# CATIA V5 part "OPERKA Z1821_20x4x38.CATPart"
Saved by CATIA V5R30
Part number: OPERKA MENSI Z1821/20x4x38
Bounding box of the stored display mesh (mm): x -7.677 to 3.495, y -9.397 to 9.603, z -19 to 19
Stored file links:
  C:\Users\ondra\Desktop\PŘÍLOHA P III\CATIA\OPERKA Z1821_20x4x38.CATPart
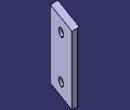
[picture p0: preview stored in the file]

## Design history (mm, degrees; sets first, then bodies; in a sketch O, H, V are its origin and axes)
Set1
  DatumSurface1 to DatumSurface19 "Z1821/20"
  Plane1: type Tangent, Support DatumSurface15, RefPoint vertex [face of DatumSurface19]
  Plane2: type Tangent, Support DatumSurface14, RefPoint vertex [face of DatumSurface18]
  Plane3: type Tangent, Support DatumSurface18, RefPoint vertex [face of DatumSurface18]
  Plane4: type Tangent, Support DatumSurface17, RefPoint vertex [face of DatumSurface19]
  Plane5: type Tangent, Support DatumSurface17, RefPoint vertex [face of DatumSurface19]
  Join1: Elements (DatumSurface1; DatumSurface2; DatumSurface3; DatumSurface4; DatumSurface5; DatumSurface6; DatumSurface7; DatumSurface8; DatumSurface9; DatumSurface10; DatumSurface11; DatumSurface12; DatumSurface13; DatumSurface14; DatumSurface15; DatumSurface16; DatumSurface17; DatumSurface18; DatumSurface19)
Body1 (main body)
  CloseSurface1: CloseElement Join1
